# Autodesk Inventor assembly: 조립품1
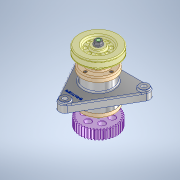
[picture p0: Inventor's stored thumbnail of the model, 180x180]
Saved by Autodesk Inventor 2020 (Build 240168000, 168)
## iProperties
Created: 2023-04
Part Number: 조립품1
Document SubType Name: Assembly
Designer: 101-13
Author: 101-13
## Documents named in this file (11)
- C:\Users\101-13\Desktop\730407V1018\조립품1.iam
- C:\Users\101-13\Desktop\730407V1018\본체.ipt
- C:\Users\101-13\Desktop\730407V1018\오일 실 20 32 8.ipt
- C:\Users\101-13\Desktop\730407V1018\커버.ipt
- C:\Users\101-13\Desktop\730407V1018\베어링 6204.ipt
- C:\Users\101-13\Desktop\730407V1018\볼트 M4 x 12.ipt
- C:\Users\101-13\Desktop\730407V1018\축.ipt
- C:\Users\101-13\Desktop\730407V1018\묻힘키 5x5x16.ipt
- C:\Users\101-13\Desktop\730407V1018\v-벨트풀리.ipt
- C:\Users\101-13\Desktop\730407V1018\6각 플랜지 너트 M10.ipt
- C:\Users\101-13\Desktop\730407V1018\스퍼기어.ipt
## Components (3 placed, 2 different names)
1. v-벨트풀리:1 — 각도:2
2. 6각 플랜지 너트 M10:1
3. 6각 플랜지 너트 M10:2
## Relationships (1: Angle 1)
- 각도:2 [Angle]: v-벨트풀리:1
